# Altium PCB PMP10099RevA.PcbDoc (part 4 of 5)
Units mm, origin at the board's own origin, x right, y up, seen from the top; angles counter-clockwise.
Board outline 227.58 x 89.92 mm, 2 copper layers (Top Layer, Bottom Layer), stack 1.575 mm thick; 558 components, 261 nets, 1374 pads, 560 vias.
Unrouted connection lines stored in the file: 7.
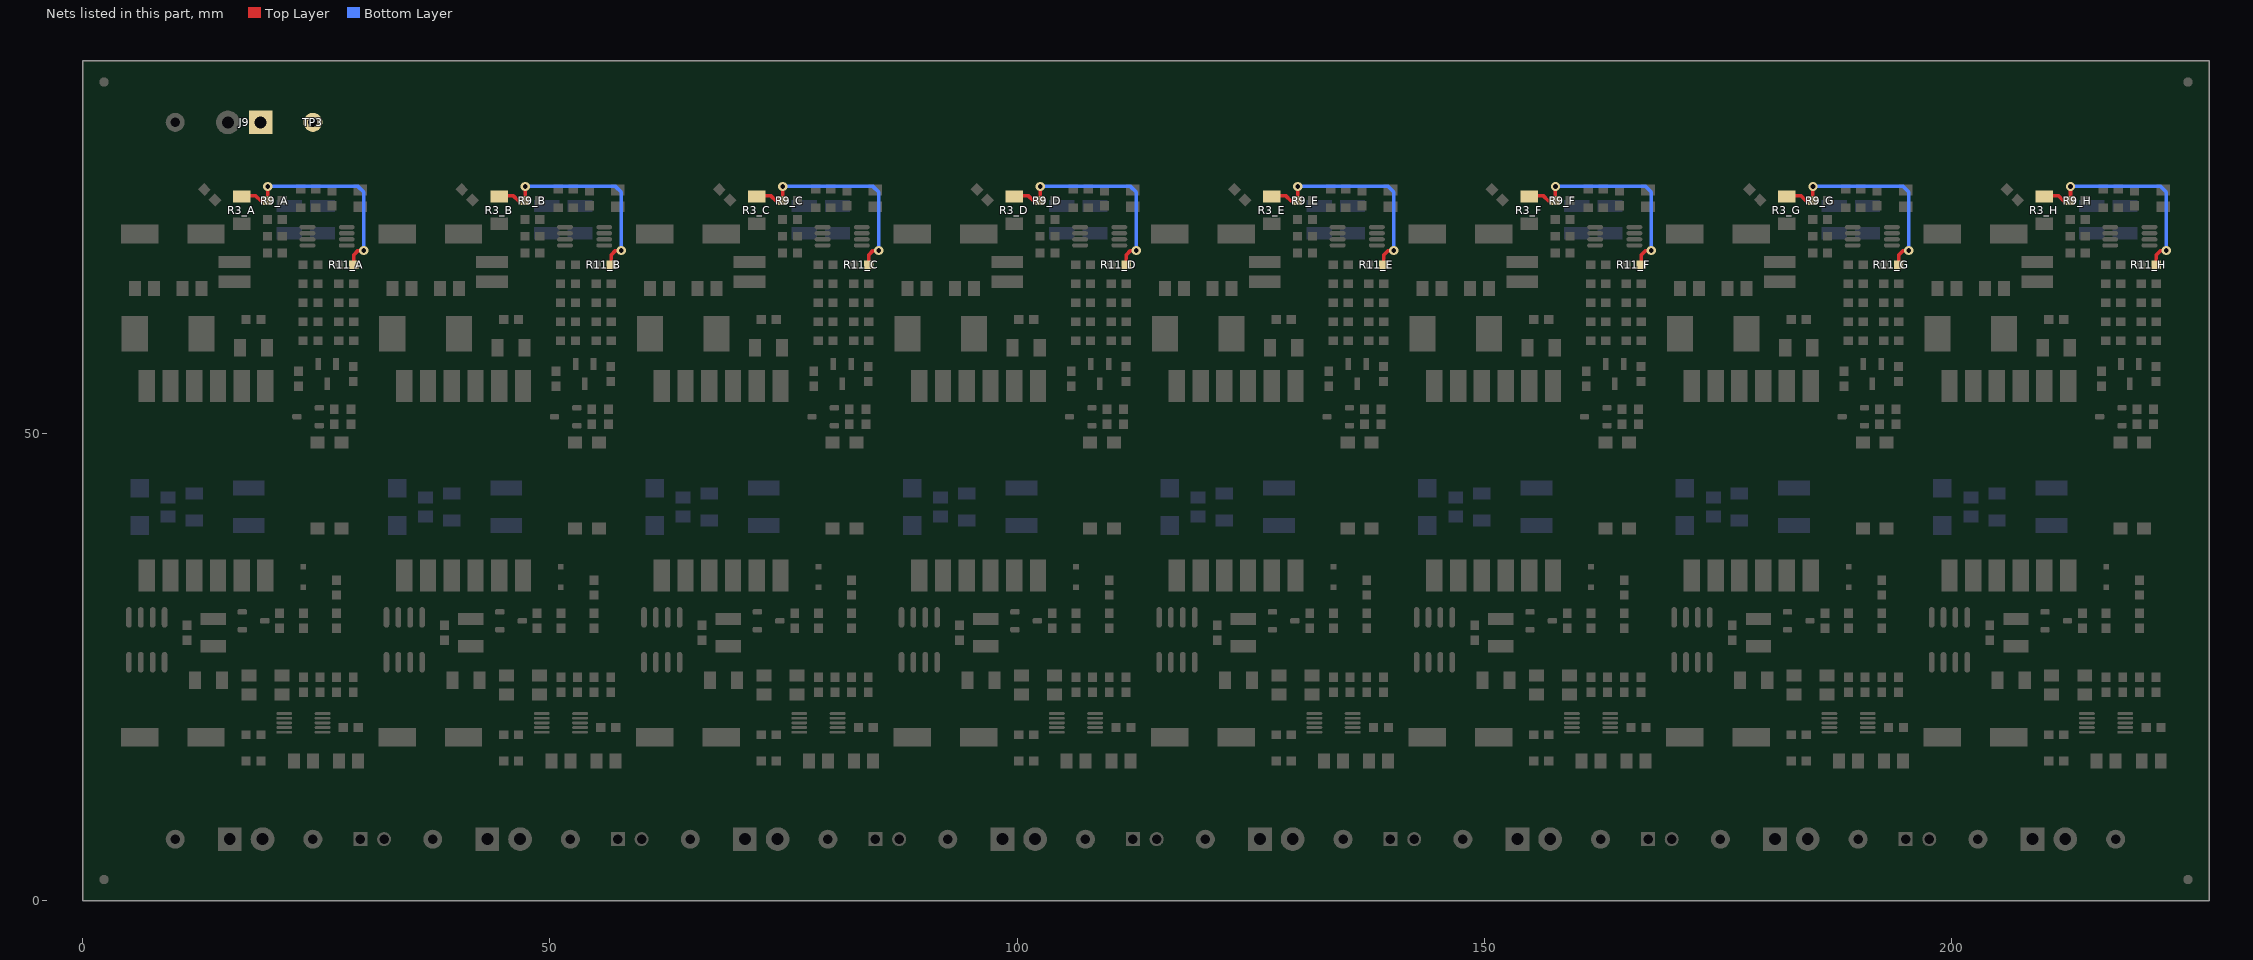
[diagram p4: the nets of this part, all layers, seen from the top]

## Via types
v1: diameter 1, hole 0.5, Top Layer to Bottom Layer, 560 vias

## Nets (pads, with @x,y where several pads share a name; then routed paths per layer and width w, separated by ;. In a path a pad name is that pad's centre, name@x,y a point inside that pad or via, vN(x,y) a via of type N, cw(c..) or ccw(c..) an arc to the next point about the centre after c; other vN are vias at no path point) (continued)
VOUT: J9.1 R3_A.2 R3_B.2 R3_C.2 R3_D.2 R3_E.2 R3_F.2 R3_G.2 R3_H.2 R9_A.2 R9_B.2 R9_C.2 R9_D.2 R9_E.2 R9_F.2 R9_G.2 R9_H.2 R11_A.2 R11_B.2 R11_C.2 R11_D.2 R11_E.2 R11_F.2 R11_G.2 R11_H.2 TP3.1 | length 188.9
  Top Layer w0.381: R3_A.2@17.018,75.364 17.092,75.438 18.542,75.438 19.05,74.93 R9_A.2@19.774,74.93 19.812,74.968 v1(19.812,76.454) ; R11_A.2@28.994,68.072 28.994,69.126 29.464,69.596 v1(30.066,69.596) ; R3_B.2@44.577,75.364 44.651,75.438 46.101,75.438 46.609,74.93 R9_B.2@47.333,74.93 47.371,74.968 v1(47.371,76.454) ; R11_B.2@56.553,68.072 56.553,69.126 57.023,69.596 v1(57.625,69.596) ; R3_C.2@72.136,75.364 72.21,75.438 73.66,75.438 74.168,74.93 R9_C.2@74.892,74.93 74.93,74.968 v1(74.93,76.454) ; R11_C.2@84.112,68.072 84.112,69.126 84.582,69.596 v1(85.184,69.596) ; R3_D.2@99.695,75.364 99.769,75.438 101.219,75.438 101.727,74.93 R9_D.2@102.451,74.93 102.489,74.968 v1(102.489,76.454) ; R11_D.2@111.671,68.072 111.671,69.126 112.141,69.596 v1(112.743,69.596) ; R3_E.2@127.254,75.364 127.328,75.438 128.778,75.438 129.286,74.93 R9_E.2@130.01,74.93 130.048,74.968 v1(130.048,76.454) ; R11_E.2@139.23,68.072 139.23,69.126 139.7,69.596 v1(140.302,69.596) ; R3_F.2@154.813,75.364 154.887,75.438 156.337,75.438 156.845,74.93 R9_F.2@157.569,74.93 157.607,74.968 v1(157.607,76.454) ; R11_F.2@166.789,68.072 166.789,69.126 167.259,69.596 v1(167.861,69.596) ; R3_G.2@182.372,75.364 182.446,75.438 183.896,75.438 184.404,74.93 R9_G.2@185.128,74.93 185.166,74.968 v1(185.166,76.454) ; R11_G.2@194.348,68.072 194.348,69.126 194.818,69.596 v1(195.42,69.596) ; R3_H.2@209.931,75.364 210.005,75.438 211.455,75.438 211.963,74.93 R9_H.2@212.687,74.93 212.725,74.968 v1(212.725,76.454) ; R11_H.2@221.907,68.072 221.907,69.126 222.377,69.596 v1(222.979,69.596)
  Bottom Layer w0.381: v1(19.812,76.454) 27.824,76.454 27.825,76.456 28.563,76.456 28.564,76.454 29.464,76.454 30.066,75.852 v1(30.066,69.596) ; v1(47.371,76.454) 55.383,76.454 55.384,76.456 56.122,76.456 56.123,76.454 57.023,76.454 57.625,75.852 v1(57.625,69.596) ; v1(74.93,76.454) 82.942,76.454 82.943,76.456 83.681,76.456 83.682,76.454 84.582,76.454 85.184,75.852 v1(85.184,69.596) ; v1(102.489,76.454) 110.501,76.454 110.502,76.456 111.24,76.456 111.241,76.454 112.141,76.454 112.743,75.852 v1(112.743,69.596) ; v1(130.048,76.454) 138.06,76.454 138.061,76.456 138.799,76.456 138.8,76.454 139.7,76.454 140.302,75.852 v1(140.302,69.596) ; v1(157.607,76.454) 165.619,76.454 165.62,76.456 166.358,76.456 166.359,76.454 167.259,76.454 167.861,75.852 v1(167.861,69.596) ; v1(185.166,76.454) 193.178,76.454 193.179,76.456 193.917,76.456 193.918,76.454 194.818,76.454 195.42,75.852 v1(195.42,69.596) ; v1(212.725,76.454) 220.737,76.454 220.738,76.456 221.476,76.456 221.477,76.454 222.377,76.454 222.979,75.852 v1(222.979,69.596)
pads on no net: D2_A.2 D2_B.2 D2_C.2 D2_D.2 D2_E.2 D2_F.2 D2_G.2 D2_H.2 D5_A.2 D5_B.2 D5_C.2 D5_D.2 D5_E.2 D5_F.2 D5_G.2 D5_H.2 FID1.1 FID2.1 FID3.1 FID4.1 T1_A.2 T1_A.4 T1_A.8 T1_A.9 T1_A.10 T1_A.11 T1_B.2 T1_B.4 T1_B.8 T1_B.9 T1_B.10 T1_B.11 T1_C.2 T1_C.4 T1_C.8 T1_C.9 T1_C.10 T1_C.11 T1_D.2 T1_D.4 T1_D.8 T1_D.9 T1_D.10 T1_D.11 T1_E.2 T1_E.4 T1_E.8 T1_E.9 T1_E.10 T1_E.11 T1_F.2 T1_F.4 T1_F.8 T1_F.9 T1_F.10 T1_F.11 T1_G.2 T1_G.4 T1_G.8 T1_G.9 T1_G.10 T1_G.11 T1_H.2 T1_H.4 T1_H.8 T1_H.9 T1_H.10 T1_H.11

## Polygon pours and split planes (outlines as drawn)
RTN on Bottom Layer "Bottom Layer-No Net 4" (solid, remove dead copper, pour order 381): 30.48,12.954 30.48,40.64 22.098,40.64 22.098,37.338 25.146,37.338 25.146,32.512 16.256,32.512 16.256,12.954
GND on Bottom Layer "Bottom Layer-No Net 10" (solid, remove dead copper, pour order 469): 15.748,43.18 19.812,43.18 19.812,46.99 15.748,46.99
RTN on Bottom Layer "Bottom Layer-No Net 9" (solid, remove dead copper, pour order 453): 19.812,41.148 19.812,33.528 15.748,33.528 15.748,41.148
NetC4_A_2 on Bottom Layer "Bottom Layer-No Net 7" (solid, remove dead copper, pour order 421): 4.318,45.466 13.462,45.466 13.462,42.418 4.318,42.418
NetD1_A_2 on Bottom Layer "Bottom Layer-No Net 8" (solid, remove dead copper, pour order 437): 7.874,37.084 7.874,41.91 4.318,41.91 4.318,37.084
VIN on Bottom Layer "Bottom Layer-No Net 6" (solid, remove dead copper, pour order 405): 13.462,37.084 13.462,41.91 8.128,41.91 8.128,37.084
VIN on Bottom Layer "Bottom Layer-No Net 3" (solid, remove dead copper, pour order 509): 15.24,32.512 4.064,32.512 4.064,12.954 8.382,12.954 8.382,28.956 15.24,28.956
RTN on Bottom Layer "Bottom Layer-No Net 5" (solid, remove dead copper, pour order 397): 22.098,34.036 22.098,30.353 18.161,26.416 15.748,26.416 15.748,34.036
GND on Bottom Layer "Bottom Layer-No Net" (solid, remove dead copper, pour order 357): 30.48,48.26 30.48,76.962 19.05,76.962 19.05,67.31 21.844,67.31 21.844,48.26
GND on Bottom Layer "Bottom Layer-No Net 1" (solid, remove dead copper, pour order 365): 4.064,76.962 18.034,76.962 18.034,66.294 22.352,66.294 22.352,62.992 11.938,62.992 11.938,67.056 11.43,67.564 4.064,67.564
NetC7_A_1 on Bottom Layer "Bottom Layer-No Net 2" (solid, remove dead copper, pour order 373): 8.636,62.484 8.636,53.086 21.336,53.086 21.336,62.484
VIN on Bottom Layer "Bottom Layer-No Net 11" (solid, remove dead copper, pour order 557): 30.48,10.414 30.48,3.048 4.064,3.048 4.064,10.414
VIN on Bottom Layer "Bottom Layer-No Net 11" (solid, remove dead copper, pour order 564): 85.598,10.414 85.598,3.048 59.182,3.048 59.182,10.414
NetC7_A_1 on Bottom Layer "Bottom Layer-No Net 2" (solid, remove dead copper, pour order 380): 63.754,62.484 63.754,53.086 76.454,53.086 76.454,62.484
GND on Bottom Layer "Bottom Layer-No Net 1" (solid, remove dead copper, pour order 372): 59.182,76.962 73.152,76.962 73.152,66.294 77.47,66.294 77.47,62.992 67.056,62.992 67.056,67.056 66.548,67.564 59.182,67.564
GND on Bottom Layer "Bottom Layer-No Net" (solid, remove dead copper, pour order 364): 85.598,48.26 85.598,76.962 74.168,76.962 74.168,67.31 76.962,67.31 76.962,48.26
RTN on Bottom Layer "Bottom Layer-No Net 5" (solid, remove dead copper, pour order 404): 77.216,34.036 77.216,30.353 73.279,26.416 70.866,26.416 70.866,34.036
VIN on Bottom Layer "Bottom Layer-No Net 3" (solid, remove dead copper, pour order 516): 70.358,32.512 59.182,32.512 59.182,12.954 63.5,12.954 63.5,28.956 70.358,28.956
VIN on Bottom Layer "Bottom Layer-No Net 6" (solid, remove dead copper, pour order 412): 68.58,37.084 68.58,41.91 63.246,41.91 63.246,37.084
NetD1_C_2 on Bottom Layer "Bottom Layer-No Net 8" (solid, remove dead copper, pour order 444): 62.992,37.084 62.992,41.91 59.436,41.91 59.436,37.084
NetC4_C_2 on Bottom Layer "Bottom Layer-No Net 7" (solid, remove dead copper, pour order 428): 59.436,45.466 68.58,45.466 68.58,42.418 59.436,42.418
RTN on Bottom Layer "Bottom Layer-No Net 9" (solid, remove dead copper, pour order 460): 74.93,41.148 74.93,33.528 70.866,33.528 70.866,41.148
GND on Bottom Layer "Bottom Layer-No Net 10" (solid, remove dead copper, pour order 476): 70.866,43.18 74.93,43.18 74.93,46.99 70.866,46.99
RTN on Bottom Layer "Bottom Layer-No Net 4" (solid, remove dead copper, pour order 388): 85.598,12.954 85.598,40.64 77.216,40.64 77.216,37.338 80.264,37.338 80.264,32.512 71.374,32.512 71.374,12.954
VIN on Bottom Layer "Bottom Layer-No Net 11" (solid, remove dead copper, pour order 563): 113.157,10.414 113.157,3.048 86.741,3.048 86.741,10.414
NetC7_A_1 on Bottom Layer "Bottom Layer-No Net 2" (solid, remove dead copper, pour order 379): 91.313,62.484 91.313,53.086 104.013,53.086 104.013,62.484
GND on Bottom Layer "Bottom Layer-No Net 1" (solid, remove dead copper, pour order 371): 86.741,76.962 100.711,76.962 100.711,66.294 105.029,66.294 105.029,62.992 94.615,62.992 94.615,67.056 94.107,67.564 86.741,67.564
GND on Bottom Layer "Bottom Layer-No Net" (solid, remove dead copper, pour order 363): 113.157,48.26 113.157,76.962 101.727,76.962 101.727,67.31 104.521,67.31 104.521,48.26
RTN on Bottom Layer "Bottom Layer-No Net 5" (solid, remove dead copper, pour order 403): 104.775,34.036 104.775,30.353 100.838,26.416 98.425,26.416 98.425,34.036
VIN on Bottom Layer "Bottom Layer-No Net 3" (solid, remove dead copper, pour order 515): 97.917,32.512 86.741,32.512 86.741,12.954 91.059,12.954 91.059,28.956 97.917,28.956
VIN on Bottom Layer "Bottom Layer-No Net 6" (solid, remove dead copper, pour order 411): 96.139,37.084 96.139,41.91 90.805,41.91 90.805,37.084
NetD1_D_2 on Bottom Layer "Bottom Layer-No Net 8" (solid, remove dead copper, pour order 443): 90.551,37.084 90.551,41.91 86.995,41.91 86.995,37.084
NetC4_D_2 on Bottom Layer "Bottom Layer-No Net 7" (solid, remove dead copper, pour order 427): 86.995,45.466 96.139,45.466 96.139,42.418 86.995,42.418
RTN on Bottom Layer "Bottom Layer-No Net 9" (solid, remove dead copper, pour order 459): 102.489,41.148 102.489,33.528 98.425,33.528 98.425,41.148
GND on Bottom Layer "Bottom Layer-No Net 10" (solid, remove dead copper, pour order 475): 98.425,43.18 102.489,43.18 102.489,46.99 98.425,46.99
RTN on Bottom Layer "Bottom Layer-No Net 4" (solid, remove dead copper, pour order 387): 113.157,12.954 113.157,40.64 104.775,40.64 104.775,37.338 107.823,37.338 107.823,32.512 98.933,32.512 98.933,12.954
VIN on Bottom Layer "Bottom Layer-No Net 11" (solid, remove dead copper, pour order 562): 140.716,10.414 140.716,3.048 114.3,3.048 114.3,10.414
NetC7_A_1 on Bottom Layer "Bottom Layer-No Net 2" (solid, remove dead copper, pour order 378): 118.872,62.484 118.872,53.086 131.572,53.086 131.572,62.484
GND on Bottom Layer "Bottom Layer-No Net 1" (solid, remove dead copper, pour order 370): 114.3,76.962 128.27,76.962 128.27,66.294 132.588,66.294 132.588,62.992 122.174,62.992 122.174,67.056 121.666,67.564 114.3,67.564
GND on Bottom Layer "Bottom Layer-No Net" (solid, remove dead copper, pour order 362): 140.716,48.26 140.716,76.962 129.286,76.962 129.286,67.31 132.08,67.31 132.08,48.26
RTN on Bottom Layer "Bottom Layer-No Net 5" (solid, remove dead copper, pour order 402): 132.334,34.036 132.334,30.353 128.397,26.416 125.984,26.416 125.984,34.036
VIN on Bottom Layer "Bottom Layer-No Net 3" (solid, remove dead copper, pour order 514): 125.476,32.512 114.3,32.512 114.3,12.954 118.618,12.954 118.618,28.956 125.476,28.956
VIN on Bottom Layer "Bottom Layer-No Net 6" (solid, remove dead copper, pour order 410): 123.698,37.084 123.698,41.91 118.364,41.91 118.364,37.084
NetD1_E_2 on Bottom Layer "Bottom Layer-No Net 8" (solid, remove dead copper, pour order 442): 118.11,37.084 118.11,41.91 114.554,41.91 114.554,37.084
NetC4_E_2 on Bottom Layer "Bottom Layer-No Net 7" (solid, remove dead copper, pour order 426): 114.554,45.466 123.698,45.466 123.698,42.418 114.554,42.418
RTN on Bottom Layer "Bottom Layer-No Net 9" (solid, remove dead copper, pour order 458): 130.048,41.148 130.048,33.528 125.984,33.528 125.984,41.148
GND on Bottom Layer "Bottom Layer-No Net 10" (solid, remove dead copper, pour order 474): 125.984,43.18 130.048,43.18 130.048,46.99 125.984,46.99
RTN on Bottom Layer "Bottom Layer-No Net 4" (solid, remove dead copper, pour order 386): 140.716,12.954 140.716,40.64 132.334,40.64 132.334,37.338 135.382,37.338 135.382,32.512 126.492,32.512 126.492,12.954
VIN on Bottom Layer "Bottom Layer-No Net 11" (solid, remove dead copper, pour order 561): 168.275,10.414 168.275,3.048 141.859,3.048 141.859,10.414
NetC7_A_1 on Bottom Layer "Bottom Layer-No Net 2" (solid, remove dead copper, pour order 377): 146.431,62.484 146.431,53.086 159.131,53.086 159.131,62.484
GND on Bottom Layer "Bottom Layer-No Net 1" (solid, remove dead copper, pour order 369): 141.859,76.962 155.829,76.962 155.829,66.294 160.147,66.294 160.147,62.992 149.733,62.992 149.733,67.056 149.225,67.564 141.859,67.564
GND on Bottom Layer "Bottom Layer-No Net" (solid, remove dead copper, pour order 361): 168.275,48.26 168.275,76.962 156.845,76.962 156.845,67.31 159.639,67.31 159.639,48.26
RTN on Bottom Layer "Bottom Layer-No Net 5" (solid, remove dead copper, pour order 401): 159.893,34.036 159.893,30.353 155.956,26.416 153.543,26.416 153.543,34.036
VIN on Bottom Layer "Bottom Layer-No Net 3" (solid, remove dead copper, pour order 513): 153.035,32.512 141.859,32.512 141.859,12.954 146.177,12.954 146.177,28.956 153.035,28.956
VIN on Bottom Layer "Bottom Layer-No Net 6" (solid, remove dead copper, pour order 409): 151.257,37.084 151.257,41.91 145.923,41.91 145.923,37.084
NetD1_F_2 on Bottom Layer "Bottom Layer-No Net 8" (solid, remove dead copper, pour order 441): 145.669,37.084 145.669,41.91 142.113,41.91 142.113,37.084
NetC4_F_2 on Bottom Layer "Bottom Layer-No Net 7" (solid, remove dead copper, pour order 425): 142.113,45.466 151.257,45.466 151.257,42.418 142.113,42.418
RTN on Bottom Layer "Bottom Layer-No Net 9" (solid, remove dead copper, pour order 457): 157.607,41.148 157.607,33.528 153.543,33.528 153.543,41.148
GND on Bottom Layer "Bottom Layer-No Net 10" (solid, remove dead copper, pour order 473): 153.543,43.18 157.607,43.18 157.607,46.99 153.543,46.99
RTN on Bottom Layer "Bottom Layer-No Net 4" (solid, remove dead copper, pour order 385): 168.275,12.954 168.275,40.64 159.893,40.64 159.893,37.338 162.941,37.338 162.941,32.512 154.051,32.512 154.051,12.954
VIN on Bottom Layer "Bottom Layer-No Net 11" (solid, remove dead copper, pour order 560): 195.834,10.414 195.834,3.048 169.418,3.048 169.418,10.414
NetC7_A_1 on Bottom Layer "Bottom Layer-No Net 2" (solid, remove dead copper, pour order 376): 173.99,62.484 173.99,53.086 186.69,53.086 186.69,62.484
GND on Bottom Layer "Bottom Layer-No Net 1" (solid, remove dead copper, pour order 368): 169.418,76.962 183.388,76.962 183.388,66.294 187.706,66.294 187.706,62.992 177.292,62.992 177.292,67.056 176.784,67.564 169.418,67.564
GND on Bottom Layer "Bottom Layer-No Net" (solid, remove dead copper, pour order 360): 195.834,48.26 195.834,76.962 184.404,76.962 184.404,67.31 187.198,67.31 187.198,48.26
RTN on Bottom Layer "Bottom Layer-No Net 5" (solid, remove dead copper, pour order 400): 187.452,34.036 187.452,30.353 183.515,26.416 181.102,26.416 181.102,34.036
VIN on Bottom Layer "Bottom Layer-No Net 3" (solid, remove dead copper, pour order 512): 180.594,32.512 169.418,32.512 169.418,12.954 173.736,12.954 173.736,28.956 180.594,28.956
VIN on Bottom Layer "Bottom Layer-No Net 6" (solid, remove dead copper, pour order 408): 178.816,37.084 178.816,41.91 173.482,41.91 173.482,37.084
NetD1_G_2 on Bottom Layer "Bottom Layer-No Net 8" (solid, remove dead copper, pour order 440): 173.228,37.084 173.228,41.91 169.672,41.91 169.672,37.084
NetC4_G_2 on Bottom Layer "Bottom Layer-No Net 7" (solid, remove dead copper, pour order 424): 169.672,45.466 178.816,45.466 178.816,42.418 169.672,42.418
RTN on Bottom Layer "Bottom Layer-No Net 9" (solid, remove dead copper, pour order 456): 185.166,41.148 185.166,33.528 181.102,33.528 181.102,41.148
GND on Bottom Layer "Bottom Layer-No Net 10" (solid, remove dead copper, pour order 472): 181.102,43.18 185.166,43.18 185.166,46.99 181.102,46.99
RTN on Bottom Layer "Bottom Layer-No Net 4" (solid, remove dead copper, pour order 384): 195.834,12.954 195.834,40.64 187.452,40.64 187.452,37.338 190.5,37.338 190.5,32.512 181.61,32.512 181.61,12.954
VIN on Bottom Layer "Bottom Layer-No Net 11" (solid, remove dead copper, pour order 559): 223.393,10.414 223.393,3.048 196.977,3.048 196.977,10.414
NetC7_A_1 on Bottom Layer "Bottom Layer-No Net 2" (solid, remove dead copper, pour order 375): 201.549,62.484 201.549,53.086 214.249,53.086 214.249,62.484
GND on Bottom Layer "Bottom Layer-No Net 1" (solid, remove dead copper, pour order 367): 196.977,76.962 210.947,76.962 210.947,66.294 215.265,66.294 215.265,62.992 204.851,62.992 204.851,67.056 204.343,67.564 196.977,67.564
GND on Bottom Layer "Bottom Layer-No Net" (solid, remove dead copper, pour order 359): 223.393,48.26 223.393,76.962 211.963,76.962 211.963,67.31 214.757,67.31 214.757,48.26
RTN on Bottom Layer "Bottom Layer-No Net 5" (solid, remove dead copper, pour order 399): 215.011,34.036 215.011,30.353 211.074,26.416 208.661,26.416 208.661,34.036
VIN on Bottom Layer "Bottom Layer-No Net 3" (solid, remove dead copper, pour order 511): 208.153,32.512 196.977,32.512 196.977,12.954 201.295,12.954 201.295,28.956 208.153,28.956
VIN on Bottom Layer "Bottom Layer-No Net 6" (solid, remove dead copper, pour order 407): 206.375,37.084 206.375,41.91 201.041,41.91 201.041,37.084
NetD1_H_2 on Bottom Layer "Bottom Layer-No Net 8" (solid, remove dead copper, pour order 439): 200.787,37.084 200.787,41.91 197.231,41.91 197.231,37.084
NetC4_H_2 on Bottom Layer "Bottom Layer-No Net 7" (solid, remove dead copper, pour order 423): 197.231,45.466 206.375,45.466 206.375,42.418 197.231,42.418
RTN on Bottom Layer "Bottom Layer-No Net 9" (solid, remove dead copper, pour order 455): 212.725,41.148 212.725,33.528 208.661,33.528 208.661,41.148
GND on Bottom Layer "Bottom Layer-No Net 10" (solid, remove dead copper, pour order 471): 208.661,43.18 212.725,43.18 212.725,46.99 208.661,46.99
RTN on Bottom Layer "Bottom Layer-No Net 4" (solid, remove dead copper, pour order 383): 223.393,12.954 223.393,40.64 215.011,40.64 215.011,37.338 218.059,37.338 218.059,32.512 209.169,32.512 209.169,12.954
VIN on Bottom Layer "Bottom Layer-No Net 11" (solid, remove dead copper, pour order 558): 58.039,10.414 58.039,3.048 31.623,3.048 31.623,10.414
NetC7_A_1 on Bottom Layer "Bottom Layer-No Net 2" (solid, remove dead copper, pour order 374): 36.195,62.484 36.195,53.086 48.895,53.086 48.895,62.484
GND on Bottom Layer "Bottom Layer-No Net 1" (solid, remove dead copper, pour order 366): 31.623,76.962 45.593,76.962 45.593,66.294 49.911,66.294 49.911,62.992 39.497,62.992 39.497,67.056 38.989,67.564 31.623,67.564
GND on Bottom Layer "Bottom Layer-No Net" (solid, remove dead copper, pour order 358): 58.039,48.26 58.039,76.962 46.609,76.962 46.609,67.31 49.403,67.31 49.403,48.26
RTN on Bottom Layer "Bottom Layer-No Net 5" (solid, remove dead copper, pour order 398): 49.657,34.036 49.657,30.353 45.72,26.416 43.307,26.416 43.307,34.036
VIN on Bottom Layer "Bottom Layer-No Net 3" (solid, remove dead copper, pour order 510): 42.799,32.512 31.623,32.512 31.623,12.954 35.941,12.954 35.941,28.956 42.799,28.956
VIN on Bottom Layer "Bottom Layer-No Net 6" (solid, remove dead copper, pour order 406): 41.021,37.084 41.021,41.91 35.687,41.91 35.687,37.084
NetD1_B_2 on Bottom Layer "Bottom Layer-No Net 8" (solid, remove dead copper, pour order 438): 35.433,37.084 35.433,41.91 31.877,41.91 31.877,37.084
NetC4_B_2 on Bottom Layer "Bottom Layer-No Net 7" (solid, remove dead copper, pour order 422): 31.877,45.466 41.021,45.466 41.021,42.418 31.877,42.418
RTN on Bottom Layer "Bottom Layer-No Net 9" (solid, remove dead copper, pour order 454): 47.371,41.148 47.371,33.528 43.307,33.528 43.307,41.148
GND on Bottom Layer "Bottom Layer-No Net 10" (solid, remove dead copper, pour order 470): 43.307,43.18 47.371,43.18 47.371,46.99 43.307,46.99
RTN on Bottom Layer "Bottom Layer-No Net 4" (solid, remove dead copper, pour order 382): 58.039,12.954 58.039,40.64 49.657,40.64 49.657,37.338 52.705,37.338 52.705,32.512 43.815,32.512 43.815,12.954
GND on Bottom Layer "Bottom Layer-No Net 12" (solid, remove dead copper, pour order 580): 4.064,67.564 8.128,67.564 8.128,86.868 4.064,86.868
GND on Bottom Layer "Bottom Layer-No Net 12" (solid, pour order 579): 59.182,67.564 63.246,67.564 63.246,86.868 59.182,86.868
GND on Bottom Layer "Bottom Layer-No Net 12" (solid, pour order 578): 86.741,67.564 90.805,67.564 90.805,86.868 86.741,86.868
GND on Bottom Layer "Bottom Layer-No Net 12" (solid, pour order 577): 114.259,67.549 118.323,67.549 118.323,86.853 114.259,86.853
GND on Bottom Layer "Bottom Layer-No Net 12" (solid, pour order 576): 141.859,67.564 145.923,67.564 145.923,86.868 141.859,86.868
GND on Bottom Layer "Bottom Layer-No Net 12" (solid, pour order 575): 169.418,67.564 173.482,67.564 173.482,86.868 169.418,86.868
GND on Bottom Layer "Bottom Layer-No Net 12" (solid, pour order 574): 196.977,67.564 201.041,67.564 201.041,86.868 196.977,86.868
GND on Bottom Layer "Bottom Layer-No Net 13" (solid, remove dead copper, pour order 581): 4.064,78.74 4.064,86.868 223.393,86.868 223.393,78.74
GND on Bottom Layer "Bottom Layer-No Net 12" (solid, pour order 573): 31.623,67.564 35.687,67.564 35.687,86.868 31.623,86.868
GND on Top Layer "Top Layer-No Net 21" (solid, remove dead copper, pour order 301): 29.972,48.26 29.972,67.056 21.844,67.056 21.844,48.26
RTN on Top Layer "Top Layer-No Net 20" (solid, remove dead copper, pour order 293): 22.098,40.64 22.098,37.338 25.146,37.338 25.146,26.416 24.511,25.781 24.511,23.368 29.845,23.368 29.845,40.64
NetQ1_A_1 on Top Layer "Top Layer-No Net 8" (solid, remove dead copper, pour order 429): 7.874,27.432 7.874,24.13 8.128,23.876 10.668,23.876 10.922,24.13 10.922,25.908 12.7,25.908 12.7,22.098 4.318,22.098 4.318,27.432
NetD1_A_2 on Top Layer "Top Layer-No Net 6" (solid, remove dead copper, pour order 389): 7.874,38.608 7.874,32.766 8.128,32.512 9.398,32.512 9.398,28.448 4.318,28.448 4.318,32.512 4.826,32.512 5.08,32.766 5.08,38.608
GND on Top Layer "Top Layer-No Net 17" (solid, remove dead copper, pour order 485): 21.336,53.594 21.336,46.482 19.812,44.958 15.748,44.958 15.748,48.26 18.542,51.054 18.542,53.594
VIN on Top Layer "Top Layer-No Net 9" (solid, remove dead copper, pour order 445): 10.414,38.608 13.462,38.608 13.462,37.338 12.954,36.83 12.954,32.766 13.208,32.512 15.748,32.512 15.748,28.956 10.414,28.956 10.414,32.512 10.668,32.512 10.922,32.766 10.922,36.83 10.414,37.338
RTN on Top Layer "Top Layer-No Net 10" (solid, remove dead copper, pour order 461): 10.414,28.448 18.288,28.448 18.288,26.416 15.748,26.416 15.748,12.954 10.16,12.954 10.16,21.59 13.208,21.59 13.208,25.908 12.446,26.67 10.922,26.67 10.414,27.178
RTN on Top Layer "Top Layer-No Net 16" (solid, remove dead copper, pour order 533): 22.606,19.685 22.606,19.431 20.066,19.431 20.066,19.05 18.034,19.05 18.034,17.272 14.732,17.272 14.732,20.828 20.066,20.828 20.066,19.685
NetC7_A_1 on Top Layer "Top Layer-No Net 2" (solid, remove dead copper, pour order 325): 18.034,57.658 8.636,57.658 8.636,62.738 10.414,62.738 11.938,64.262 11.938,67.056 18.034,67.056
GND on Top Layer "Top Layer-No Net 5" (solid, remove dead copper, pour order 349): 9.144,68.58 4.064,68.58 4.064,76.962 15.494,76.962 15.494,76.454 14.224,76.454 11.684,73.914 9.144,73.914
NetC6_A_1 on Top Layer "Top Layer-No Net 3" (solid, remove dead copper, pour order 333): 18.034,67.564 18.034,73.406 15.494,73.406 15.494,76.073 14.351,76.073 11.684,73.406 9.652,73.406 9.652,68.58 13.462,68.58 14.478,67.564
GND on Top Layer "Top Layer-No Net 4" (solid, remove dead copper, pour order 341): 18.542,53.086 21.336,53.086 21.336,66.294 18.542,66.294
NetQ1_A_4 on Top Layer "Top Layer-No Net 7" (solid, remove dead copper, pour order 413): 8.382,26.67 9.652,26.67 10.414,25.908 10.414,24.384 8.382,24.384
NetD2_A_1 on Top Layer "Top Layer-No Net 11" (solid, remove dead copper, pour order 477): 16.002,36.83 16.002,29.972 18.034,29.972 18.034,36.83
VIN on Top Layer "Top Layer-No Net 14" (solid, remove dead copper, pour order 517): 4.064,21.59 9.144,21.59 9.144,12.954 4.064,12.954
NetC17_A_1 on Top Layer "Top Layer-No Net 15" (solid, remove dead copper, pour order 525): 24.638,30.226 24.638,34.036 22.606,34.036 22.606,30.226
NetC11_A_1 on Top Layer "Top Layer-No Net 12" (solid, remove dead copper, pour order 493): 24.638,29.718 20.066,29.718 20.066,30.48 18.542,30.48 18.542,27.94 24.638,27.94
RTN on Top Layer "Top Layer-No Net 13" (solid, remove dead copper, pour order 501): 18.542,36.83 18.542,30.988 20.574,30.988 20.574,30.226 22.098,30.226 22.098,34.544 24.638,34.544 24.638,36.83
VIN on Top Layer "Top Layer-No Net 19" (solid, remove dead copper, pour order 549): 17.018,3.048 17.018,9.398 9.144,9.398 9.144,13.208 4.064,13.208 4.064,3.048
RTN on Top Layer "Top Layer-No Net 18" (solid, remove dead copper, pour order 541): 17.526,3.048 30.48,3.048 30.48,12.446 16.51,12.446 16.51,17.526 10.16,17.526 10.16,9.906 17.526,9.906
NetC5_A_2 on Top Layer "Top Layer-No Net" (solid, remove dead copper, pour order 309): 7.874,53.086 7.874,62.738 6.35,64.262 6.35,67.056 4.064,67.056 4.064,53.086
NetC5_A_1 on Top Layer "Top Layer-No Net 1" (solid, remove dead copper, pour order 317): 6.858,67.056 11.43,67.056 11.43,64.516 11.176,64.262 7.112,64.262 6.858,64.516
NetC5_C_1 on Top Layer "Top Layer-No Net 1" (solid, remove dead copper, pour order 324): 61.976,67.056 66.548,67.056 66.548,64.516 66.294,64.262 62.23,64.262 61.976,64.516
NetC5_C_2 on Top Layer "Top Layer-No Net" (solid, remove dead copper, pour order 316): 62.992,53.086 62.992,62.738 61.468,64.262 61.468,67.056 59.182,67.056 59.182,53.086
RTN on Top Layer "Top Layer-No Net 18" (solid, remove dead copper, pour order 548): 72.644,3.048 85.598,3.048 85.598,12.446 71.628,12.446 71.628,17.526 65.278,17.526 65.278,9.906 72.644,9.906
VIN on Top Layer "Top Layer-No Net 19" (solid, remove dead copper, pour order 556): 72.136,3.048 72.136,9.398 64.262,9.398 64.262,13.208 59.182,13.208 59.182,3.048
RTN on Top Layer "Top Layer-No Net 13" (solid, remove dead copper, pour order 508): 73.66,36.83 73.66,30.988 75.692,30.988 75.692,30.226 77.216,30.226 77.216,34.544 79.756,34.544 79.756,36.83
NetC11_C_1 on Top Layer "Top Layer-No Net 12" (solid, remove dead copper, pour order 500): 79.756,29.718 75.184,29.718 75.184,30.48 73.66,30.48 73.66,27.94 79.756,27.94
NetC17_C_1 on Top Layer "Top Layer-No Net 15" (solid, remove dead copper, pour order 532): 79.756,30.226 79.756,34.036 77.724,34.036 77.724,30.226
VIN on Top Layer "Top Layer-No Net 14" (solid, remove dead copper, pour order 524): 59.182,21.59 64.262,21.59 64.262,12.954 59.182,12.954
NetD2_C_1 on Top Layer "Top Layer-No Net 11" (solid, remove dead copper, pour order 484): 71.12,36.83 71.12,29.972 73.152,29.972 73.152,36.83
NetQ1_C_4 on Top Layer "Top Layer-No Net 7" (solid, remove dead copper, pour order 420): 63.5,26.67 64.77,26.67 65.532,25.908 65.532,24.384 63.5,24.384
GND on Top Layer "Top Layer-No Net 4" (solid, remove dead copper, pour order 348): 73.66,53.086 76.454,53.086 76.454,66.294 73.66,66.294
NetC6_C_1 on Top Layer "Top Layer-No Net 3" (solid, remove dead copper, pour order 340): 73.152,67.564 73.152,73.406 70.612,73.406 70.612,76.073 69.469,76.073 66.802,73.406 64.77,73.406 64.77,68.58 68.58,68.58 69.596,67.564
GND on Top Layer "Top Layer-No Net 5" (solid, remove dead copper, pour order 356): 64.262,68.58 59.182,68.58 59.182,76.962 70.612,76.962 70.612,76.454 69.342,76.454 66.802,73.914 64.262,73.914
NetC7_C_1 on Top Layer "Top Layer-No Net 2" (solid, remove dead copper, pour order 332): 73.152,57.658 63.754,57.658 63.754,62.738 65.532,62.738 67.056,64.262 67.056,67.056 73.152,67.056
RTN on Top Layer "Top Layer-No Net 16" (solid, remove dead copper, pour order 540): 77.724,19.685 77.724,19.431 75.184,19.431 75.184,19.05 73.152,19.05 73.152,17.272 69.85,17.272 69.85,20.828 75.184,20.828 75.184,19.685
RTN on Top Layer "Top Layer-No Net 10" (solid, remove dead copper, pour order 468): 65.532,28.448 73.406,28.448 73.406,26.416 70.866,26.416 70.866,12.954 65.278,12.954 65.278,21.59 68.326,21.59 68.326,25.908 67.564,26.67 66.04,26.67 65.532,27.178
VIN on Top Layer "Top Layer-No Net 9" (solid, remove dead copper, pour order 452): 65.532,38.608 68.58,38.608 68.58,37.338 68.072,36.83 68.072,32.766 68.326,32.512 70.866,32.512 70.866,28.956 65.532,28.956 65.532,32.512 65.786,32.512 66.04,32.766 66.04,36.83 65.532,37.338
GND on Top Layer "Top Layer-No Net 17" (solid, remove dead copper, pour order 492): 76.454,53.594 76.454,46.482 74.93,44.958 70.866,44.958 70.866,48.26 73.66,51.054 73.66,53.594
NetD1_C_2 on Top Layer "Top Layer-No Net 6" (solid, remove dead copper, pour order 396): 62.992,38.608 62.992,32.766 63.246,32.512 64.516,32.512 64.516,28.448 59.436,28.448 59.436,32.512 59.944,32.512 60.198,32.766 60.198,38.608
NetQ1_C_1 on Top Layer "Top Layer-No Net 8" (solid, remove dead copper, pour order 436): 62.992,27.432 62.992,24.13 63.246,23.876 65.786,23.876 66.04,24.13 66.04,25.908 67.818,25.908 67.818,22.098 59.436,22.098 59.436,27.432
RTN on Top Layer "Top Layer-No Net 20" (solid, remove dead copper, pour order 300): 77.216,40.64 77.216,37.338 80.264,37.338 80.264,26.416 79.629,25.781 79.629,23.368 84.963,23.368 84.963,40.64
GND on Top Layer "Top Layer-No Net 21" (solid, remove dead copper, pour order 308): 85.09,48.26 85.09,67.056 76.962,67.056 76.962,48.26
NetC5_D_1 on Top Layer "Top Layer-No Net 1" (solid, remove dead copper, pour order 323): 89.535,67.056 94.107,67.056 94.107,64.516 93.853,64.262 89.789,64.262 89.535,64.516
NetC5_D_2 on Top Layer "Top Layer-No Net" (solid, remove dead copper, pour order 315): 90.551,53.086 90.551,62.738 89.027,64.262 89.027,67.056 86.741,67.056 86.741,53.086
RTN on Top Layer "Top Layer-No Net 18" (solid, remove dead copper, pour order 547): 100.203,3.048 113.157,3.048 113.157,12.446 99.187,12.446 99.187,17.526 92.837,17.526 92.837,9.906 100.203,9.906
VIN on Top Layer "Top Layer-No Net 19" (solid, remove dead copper, pour order 555): 99.695,3.048 99.695,9.398 91.821,9.398 91.821,13.208 86.741,13.208 86.741,3.048
RTN on Top Layer "Top Layer-No Net 13" (solid, remove dead copper, pour order 507): 101.219,36.83 101.219,30.988 103.251,30.988 103.251,30.226 104.775,30.226 104.775,34.544 107.315,34.544 107.315,36.83
NetC11_D_1 on Top Layer "Top Layer-No Net 12" (solid, remove dead copper, pour order 499): 107.315,29.718 102.743,29.718 102.743,30.48 101.219,30.48 101.219,27.94 107.315,27.94
NetC17_D_1 on Top Layer "Top Layer-No Net 15" (solid, remove dead copper, pour order 531): 107.315,30.226 107.315,34.036 105.283,34.036 105.283,30.226
VIN on Top Layer "Top Layer-No Net 14" (solid, remove dead copper, pour order 523): 86.741,21.59 91.821,21.59 91.821,12.954 86.741,12.954
NetD2_D_1 on Top Layer "Top Layer-No Net 11" (solid, remove dead copper, pour order 483): 98.679,36.83 98.679,29.972 100.711,29.972 100.711,36.83
NetQ1_D_4 on Top Layer "Top Layer-No Net 7" (solid, remove dead copper, pour order 419): 91.059,26.67 92.329,26.67 93.091,25.908 93.091,24.384 91.059,24.384
GND on Top Layer "Top Layer-No Net 4" (solid, remove dead copper, pour order 347): 101.219,53.086 104.013,53.086 104.013,66.294 101.219,66.294
NetC6_D_1 on Top Layer "Top Layer-No Net 3" (solid, remove dead copper, pour order 339): 100.711,67.564 100.711,73.406 98.171,73.406 98.171,76.073 97.028,76.073 94.361,73.406 92.329,73.406 92.329,68.58 96.139,68.58 97.155,67.564
GND on Top Layer "Top Layer-No Net 5" (solid, remove dead copper, pour order 355): 91.821,68.58 86.741,68.58 86.741,76.962 98.171,76.962 98.171,76.454 96.901,76.454 94.361,73.914 91.821,73.914
NetC7_D_1 on Top Layer "Top Layer-No Net 2" (solid, remove dead copper, pour order 331): 100.711,57.658 91.313,57.658 91.313,62.738 93.091,62.738 94.615,64.262 94.615,67.056 100.711,67.056
RTN on Top Layer "Top Layer-No Net 16" (solid, remove dead copper, pour order 539): 105.283,19.685 105.283,19.431 102.743,19.431 102.743,19.05 100.711,19.05 100.711,17.272 97.409,17.272 97.409,20.828 102.743,20.828 102.743,19.685
RTN on Top Layer "Top Layer-No Net 10" (solid, remove dead copper, pour order 467): 93.091,28.448 100.965,28.448 100.965,26.416 98.425,26.416 98.425,12.954 92.837,12.954 92.837,21.59 95.885,21.59 95.885,25.908 95.123,26.67 93.599,26.67 93.091,27.178
VIN on Top Layer "Top Layer-No Net 9" (solid, remove dead copper, pour order 451): 93.091,38.608 96.139,38.608 96.139,37.338 95.631,36.83 95.631,32.766 95.885,32.512 98.425,32.512 98.425,28.956 93.091,28.956 93.091,32.512 93.345,32.512 93.599,32.766 93.599,36.83 93.091,37.338
GND on Top Layer "Top Layer-No Net 17" (solid, remove dead copper, pour order 491): 104.013,53.594 104.013,46.482 102.489,44.958 98.425,44.958 98.425,48.26 101.219,51.054 101.219,53.594
NetD1_D_2 on Top Layer "Top Layer-No Net 6" (solid, remove dead copper, pour order 395): 90.551,38.608 90.551,32.766 90.805,32.512 92.075,32.512 92.075,28.448 86.995,28.448 86.995,32.512 87.503,32.512 87.757,32.766 87.757,38.608
NetQ1_D_1 on Top Layer "Top Layer-No Net 8" (solid, remove dead copper, pour order 435): 90.551,27.432 90.551,24.13 90.805,23.876 93.345,23.876 93.599,24.13 93.599,25.908 95.377,25.908 95.377,22.098 86.995,22.098 86.995,27.432
RTN on Top Layer "Top Layer-No Net 20" (solid, remove dead copper, pour order 299): 104.775,40.64 104.775,37.338 107.823,37.338 107.823,26.416 107.188,25.781 107.188,23.368 112.522,23.368 112.522,40.64
GND on Top Layer "Top Layer-No Net 21" (solid, remove dead copper, pour order 307): 112.649,48.26 112.649,67.056 104.521,67.056 104.521,48.26
NetC5_E_1 on Top Layer "Top Layer-No Net 1" (solid, remove dead copper, pour order 322): 117.094,67.056 121.666,67.056 121.666,64.516 121.412,64.262 117.348,64.262 117.094,64.516
NetC5_E_2 on Top Layer "Top Layer-No Net" (solid, remove dead copper, pour order 314): 118.11,53.086 118.11,62.738 116.586,64.262 116.586,67.056 114.3,67.056 114.3,53.086
RTN on Top Layer "Top Layer-No Net 18" (solid, remove dead copper, pour order 546): 127.762,3.048 140.716,3.048 140.716,12.446 126.746,12.446 126.746,17.526 120.396,17.526 120.396,9.906 127.762,9.906
VIN on Top Layer "Top Layer-No Net 19" (solid, remove dead copper, pour order 554): 127.254,3.048 127.254,9.398 119.38,9.398 119.38,13.208 114.3,13.208 114.3,3.048
RTN on Top Layer "Top Layer-No Net 13" (solid, remove dead copper, pour order 506): 128.778,36.83 128.778,30.988 130.81,30.988 130.81,30.226 132.334,30.226 132.334,34.544 134.874,34.544 134.874,36.83
NetC11_E_1 on Top Layer "Top Layer-No Net 12" (solid, remove dead copper, pour order 498): 134.874,29.718 130.302,29.718 130.302,30.48 128.778,30.48 128.778,27.94 134.874,27.94
NetC17_E_1 on Top Layer "Top Layer-No Net 15" (solid, remove dead copper, pour order 530): 134.874,30.226 134.874,34.036 132.842,34.036 132.842,30.226
VIN on Top Layer "Top Layer-No Net 14" (solid, remove dead copper, pour order 522): 114.3,21.59 119.38,21.59 119.38,12.954 114.3,12.954
NetD2_E_1 on Top Layer "Top Layer-No Net 11" (solid, remove dead copper, pour order 482): 126.238,36.83 126.238,29.972 128.27,29.972 128.27,36.83
NetQ1_E_4 on Top Layer "Top Layer-No Net 7" (solid, remove dead copper, pour order 418): 118.618,26.67 119.888,26.67 120.65,25.908 120.65,24.384 118.618,24.384
GND on Top Layer "Top Layer-No Net 4" (solid, remove dead copper, pour order 346): 128.778,53.086 131.572,53.086 131.572,66.294 128.778,66.294
NetC6_E_1 on Top Layer "Top Layer-No Net 3" (solid, remove dead copper, pour order 338): 128.27,67.564 128.27,73.406 125.73,73.406 125.73,76.073 124.587,76.073 121.92,73.406 119.888,73.406 119.888,68.58 123.698,68.58 124.714,67.564
GND on Top Layer "Top Layer-No Net 5" (solid, remove dead copper, pour order 354): 119.38,68.58 114.3,68.58 114.3,76.962 125.73,76.962 125.73,76.454 124.46,76.454 121.92,73.914 119.38,73.914
NetC7_E_1 on Top Layer "Top Layer-No Net 2" (solid, remove dead copper, pour order 330): 128.27,57.658 118.872,57.658 118.872,62.738 120.65,62.738 122.174,64.262 122.174,67.056 128.27,67.056
RTN on Top Layer "Top Layer-No Net 16" (solid, remove dead copper, pour order 538): 132.842,19.685 132.842,19.431 130.302,19.431 130.302,19.05 128.27,19.05 128.27,17.272 124.968,17.272 124.968,20.828 130.302,20.828 130.302,19.685
RTN on Top Layer "Top Layer-No Net 10" (solid, remove dead copper, pour order 466): 120.65,28.448 128.524,28.448 128.524,26.416 125.984,26.416 125.984,12.954 120.396,12.954 120.396,21.59 123.444,21.59 123.444,25.908 122.682,26.67 121.158,26.67 120.65,27.178
VIN on Top Layer "Top Layer-No Net 9" (solid, remove dead copper, pour order 450): 120.65,38.608 123.698,38.608 123.698,37.338 123.19,36.83 123.19,32.766 123.444,32.512 125.984,32.512 125.984,28.956 120.65,28.956 120.65,32.512 120.904,32.512 121.158,32.766 121.158,36.83 120.65,37.338
GND on Top Layer "Top Layer-No Net 17" (solid, remove dead copper, pour order 490): 131.572,53.594 131.572,46.482 130.048,44.958 125.984,44.958 125.984,48.26 128.778,51.054 128.778,53.594
NetD1_E_2 on Top Layer "Top Layer-No Net 6" (solid, remove dead copper, pour order 394): 118.11,38.608 118.11,32.766 118.364,32.512 119.634,32.512 119.634,28.448 114.554,28.448 114.554,32.512 115.062,32.512 115.316,32.766 115.316,38.608
NetQ1_E_1 on Top Layer "Top Layer-No Net 8" (solid, remove dead copper, pour order 434): 118.11,27.432 118.11,24.13 118.364,23.876 120.904,23.876 121.158,24.13 121.158,25.908 122.936,25.908 122.936,22.098 114.554,22.098 114.554,27.432
RTN on Top Layer "Top Layer-No Net 20" (solid, remove dead copper, pour order 298): 132.334,40.64 132.334,37.338 135.382,37.338 135.382,26.416 134.747,25.781 134.747,23.368 140.081,23.368 140.081,40.64
GND on Top Layer "Top Layer-No Net 21" (solid, remove dead copper, pour order 306): 140.208,48.26 140.208,67.056 132.08,67.056 132.08,48.26
NetC5_F_1 on Top Layer "Top Layer-No Net 1" (solid, remove dead copper, pour order 321): 144.653,67.056 149.225,67.056 149.225,64.516 148.971,64.262 144.907,64.262 144.653,64.516
NetC5_F_2 on Top Layer "Top Layer-No Net" (solid, remove dead copper, pour order 313): 145.669,53.086 145.669,62.738 144.145,64.262 144.145,67.056 141.859,67.056 141.859,53.086
RTN on Top Layer "Top Layer-No Net 18" (solid, remove dead copper, pour order 545): 155.321,3.048 168.275,3.048 168.275,12.446 154.305,12.446 154.305,17.526 147.955,17.526 147.955,9.906 155.321,9.906
VIN on Top Layer "Top Layer-No Net 19" (solid, remove dead copper, pour order 553): 154.813,3.048 154.813,9.398 146.939,9.398 146.939,13.208 141.859,13.208 141.859,3.048
RTN on Top Layer "Top Layer-No Net 13" (solid, remove dead copper, pour order 505): 156.337,36.83 156.337,30.988 158.369,30.988 158.369,30.226 159.893,30.226 159.893,34.544 162.433,34.544 162.433,36.83
NetC11_F_1 on Top Layer "Top Layer-No Net 12" (solid, remove dead copper, pour order 497): 162.433,29.718 157.861,29.718 157.861,30.48 156.337,30.48 156.337,27.94 162.433,27.94
NetC17_F_1 on Top Layer "Top Layer-No Net 15" (solid, remove dead copper, pour order 529): 162.433,30.226 162.433,34.036 160.401,34.036 160.401,30.226
VIN on Top Layer "Top Layer-No Net 14" (solid, remove dead copper, pour order 521): 141.859,21.59 146.939,21.59 146.939,12.954 141.859,12.954
NetD2_F_1 on Top Layer "Top Layer-No Net 11" (solid, remove dead copper, pour order 481): 153.797,36.83 153.797,29.972 155.829,29.972 155.829,36.83
NetQ1_F_4 on Top Layer "Top Layer-No Net 7" (solid, remove dead copper, pour order 417): 146.177,26.67 147.447,26.67 148.209,25.908 148.209,24.384 146.177,24.384
GND on Top Layer "Top Layer-No Net 4" (solid, remove dead copper, pour order 345): 156.337,53.086 159.131,53.086 159.131,66.294 156.337,66.294
NetC6_F_1 on Top Layer "Top Layer-No Net 3" (solid, remove dead copper, pour order 337): 155.829,67.564 155.829,73.406 153.289,73.406 153.289,76.073 152.146,76.073 149.479,73.406 147.447,73.406 147.447,68.58 151.257,68.58 152.273,67.564
GND on Top Layer "Top Layer-No Net 5" (solid, remove dead copper, pour order 353): 146.939,68.58 141.859,68.58 141.859,76.962 153.289,76.962 153.289,76.454 152.019,76.454 149.479,73.914 146.939,73.914
NetC7_F_1 on Top Layer "Top Layer-No Net 2" (solid, remove dead copper, pour order 329): 155.829,57.658 146.431,57.658 146.431,62.738 148.209,62.738 149.733,64.262 149.733,67.056 155.829,67.056
RTN on Top Layer "Top Layer-No Net 16" (solid, remove dead copper, pour order 537): 160.401,19.685 160.401,19.431 157.861,19.431 157.861,19.05 155.829,19.05 155.829,17.272 152.527,17.272 152.527,20.828 157.861,20.828 157.861,19.685
RTN on Top Layer "Top Layer-No Net 10" (solid, remove dead copper, pour order 465): 148.209,28.448 156.083,28.448 156.083,26.416 153.543,26.416 153.543,12.954 147.955,12.954 147.955,21.59 151.003,21.59 151.003,25.908 150.241,26.67 148.717,26.67 148.209,27.178
VIN on Top Layer "Top Layer-No Net 9" (solid, remove dead copper, pour order 449): 148.209,38.608 151.257,38.608 151.257,37.338 150.749,36.83 150.749,32.766 151.003,32.512 153.543,32.512 153.543,28.956 148.209,28.956 148.209,32.512 148.463,32.512 148.717,32.766 148.717,36.83 148.209,37.338
GND on Top Layer "Top Layer-No Net 17" (solid, remove dead copper, pour order 489): 159.131,53.594 159.131,46.482 157.607,44.958 153.543,44.958 153.543,48.26 156.337,51.054 156.337,53.594
NetD1_F_2 on Top Layer "Top Layer-No Net 6" (solid, remove dead copper, pour order 393): 145.669,38.608 145.669,32.766 145.923,32.512 147.193,32.512 147.193,28.448 142.113,28.448 142.113,32.512 142.621,32.512 142.875,32.766 142.875,38.608
NetQ1_F_1 on Top Layer "Top Layer-No Net 8" (solid, remove dead copper, pour order 433): 145.669,27.432 145.669,24.13 145.923,23.876 148.463,23.876 148.717,24.13 148.717,25.908 150.495,25.908 150.495,22.098 142.113,22.098 142.113,27.432
RTN on Top Layer "Top Layer-No Net 20" (solid, remove dead copper, pour order 297): 159.893,40.64 159.893,37.338 162.941,37.338 162.941,26.416 162.306,25.781 162.306,23.368 167.64,23.368 167.64,40.64
GND on Top Layer "Top Layer-No Net 21" (solid, remove dead copper, pour order 305): 167.767,48.26 167.767,67.056 159.639,67.056 159.639,48.26
NetC5_G_1 on Top Layer "Top Layer-No Net 1" (solid, remove dead copper, pour order 320): 172.212,67.056 176.784,67.056 176.784,64.516 176.53,64.262 172.466,64.262 172.212,64.516
NetC5_G_2 on Top Layer "Top Layer-No Net" (solid, remove dead copper, pour order 312): 173.228,53.086 173.228,62.738 171.704,64.262 171.704,67.056 169.418,67.056 169.418,53.086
